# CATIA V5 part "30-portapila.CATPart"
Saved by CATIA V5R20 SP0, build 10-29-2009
Part number: 30-portapila
Revision: ANY
Definition: UNKNOWN
Nomenclature: 30-portapila
Source: Unknown
Bounding box of the stored display mesh (mm): x -17.35 to 17.35, y -8.1 to 8.1, z 0 to 15.2
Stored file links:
  C:\Users\Utente\Desktop\IO LAVORO\3D X SITO CF\CUMSA\3D files CC\CCHS5328\30-portapila.CATPart
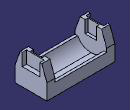
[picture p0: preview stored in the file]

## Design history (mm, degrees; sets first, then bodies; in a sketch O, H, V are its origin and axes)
Body1 "Cortar-Extruir6" (main body)
  Solid1: solid without history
